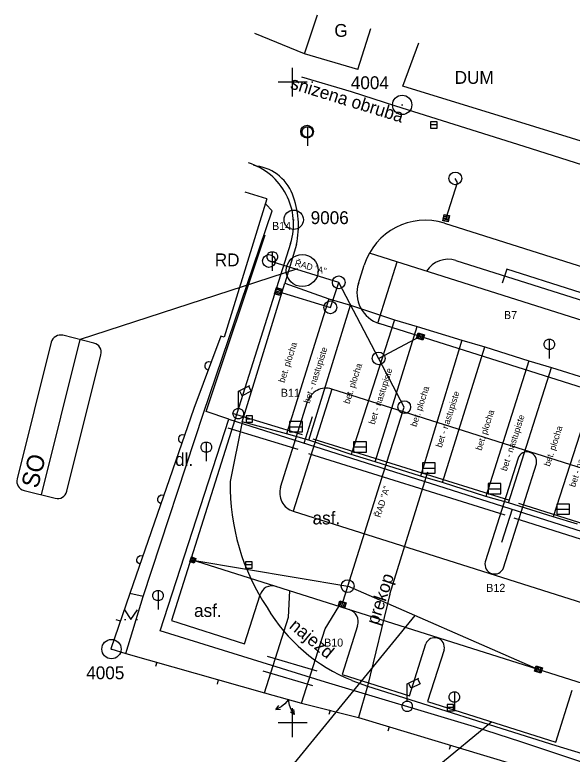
# Model space of a CAD drawing. Extents: x -733601 to -733291, y -1137892 to -1137187.
# Drawn here: x -733521.7 to -733478.2, y -1137552.5 to -1137494.7 of the extents above; entities that cross this region are included whole.
import ezdxf

# ---------------------------------------------------------------- set-up
doc = ezdxf.new("R2010")
doc.units = 0
for name, color, linetype in [('BP_NOVE_NAVRH', 7, 'Continuous'), ('BP_PBPP_pouzito_pro_map_podklady', 7, 'Continuous'), ('Default', 7, 'Continuous'), ('Krizky_Hektom_sit', 7, 'Continuous'), ('SIT_PROJ', 7, 'Continuous'), ('SIT_PUV_BUS', 7, 'Continuous')]:
    doc.layers.add(name, color=color, linetype=linetype)

# ---------------------------------------------------------------- blocks, each defined once
blk = doc.blocks.new('DOPRAVA_4$0$SYMB1230')
at = {"layer": 'Default'}
for p, q in [((-0.1, -0.329897), (-0.1, -0.020619)), ((-0.1, -0.325773), (-0.1, -0.329897)), ((0, -0.020619), (0, -0.329897)), ((0.1, -0.020619), (0.1, -0.329897))]:
    blk.add_line(p, q, dxfattribs=at)
for points in [[(-0.2, 0), (0.2, 0), (0.2, -0.35), (-0.2, -0.35)], [(-0.182831, -0.020619), (0.181696, -0.020619), (0.181696, -0.329897), (-0.182831, -0.329897)]]:
    blk.add_lwpolyline(points, close=True, dxfattribs=at)
blk = doc.blocks.new('T_PS_1_1_4')
at = {"layer": 'Default'}
blk.add_line((-0.01249, 0.00372), (0.01249, 0.00372), dxfattribs=at)
for points in [[(0.01099, 0.008), (-0.01099, 0.008)], [(-0.01249, 0.0065), (-0.01249, 0.0015)], [(0.01249, 0.0015), (0.01249, 0.0065)], [(-0.01099, 0), (0.01099, 0)]]:
    blk.add_lwpolyline(points, dxfattribs=at)
for centre, start, end in [((-0.01099, 0.0065), 90, 180), ((0.01099, 0.0065), 0, 90), ((-0.01099, 0.0015), 180, 270), ((0.01099, 0.0015), 270, 360)]:
    blk.add_arc(centre, 0.0015, start, end, dxfattribs=at)
blk.add_text('SO', height=0.0027, dxfattribs=at).set_placement((-0.01175, 0.00447))

msp = doc.modelspace()

# ---------------------------------------------------------------- linework, layer by layer
at = {"layer": 'BP_NOVE_NAVRH'}
for p, q in [((-733491.493, -1137501.774), (-733491.393, -1137501.774)), ((-733514.2, -1137544.252), (-733514.1, -1137544.252))]:
    msp.add_line(p, q, dxfattribs=at)
for centre in [(-733491.443, -1137501.774), (-733514.15, -1137544.252)]:
    msp.add_circle(centre, 0.756, dxfattribs=at)
at = {"layer": 'BP_PBPP_pouzito_pro_map_podklady'}
msp.add_line((-733499.967, -1137510.74), (-733499.867, -1137510.74), dxfattribs=at)
msp.add_circle((-733499.917, -1137510.74), 0.756, dxfattribs=at)
at = {"layer": 'Krizky_Hektom_sit'}
for p, q in [((-733500, -1137501.131), (-733500, -1137498.869)), ((-733498.869, -1137500), (-733501.131, -1137500)), ((-733500, -1137551.131), (-733500, -1137548.869)), ((-733498.869, -1137550), (-733501.131, -1137550))]:
    msp.add_line(p, q, dxfattribs=at)
at = {"layer": 'SIT_PROJ'}
for p, q in [((-733493.346, -1137518.8), (-733491.839, -1137514.036)), ((-733460.095, -1137529.321), (-733493.227, -1137518.841)), ((-733468.341, -1137533.006), (-733496.944, -1137523.958)), ((-733499.96, -1137533.492), (-733471.356, -1137542.54)), ((-733466.004, -1137550.526), (-733507.966, -1137537.253)), ((-733488.17, -1137544.301), (-733489.452, -1137548.353)), ((-733479.441, -1137551.52), (-733478.159, -1137547.468)), ((-733489.452, -1137548.353), (-733479.441, -1137551.52))]:
    msp.add_line(p, q, dxfattribs=at)
for points in [[(-733488.011, -1137510.618), (-733487.131, -1137507.826), (-733487.294, -1137507.513)], [(-733488.129, -1137511.014), (-733456.405, -1137521.049)], [(-733504.974, -1137526.312), (-733506.751, -1137525.715), (-733502.147, -1137511.903)], [(-733500.165, -1137512.59), (-733509.474, -1137542.02), (-733503.754, -1137543.829), (-733502.547, -1137540.016)], [(-733460.747, -1137528.066), (-733459.541, -1137524.252), (-733494.007, -1137513.35)], [(-733495.699, -1137539.339), (-733491.28, -1137525.366), (-733496.396, -1137515.626), (-733501.847, -1137513.955)], [(-733487.24, -1137513.917), (-733456.681, -1137523.583)], [(-733494.857, -1137515.703), (-733494.405, -1137514.273)], [(-733499.608, -1137514.568), (-733516.593, -1137520.098), (-733516.593, -1137520.098)], [(-733452.807, -1137531.541), (-733451.767, -1137530.574), (-733451.693, -1137528.596), (-733452.588, -1137526.208), (-733454.078, -1137524.418), (-733455.407, -1137523.545), (-733457.093, -1137522.916), (-733483.255, -1137514.587), (-733483.623, -1137515.683)], [(-733501.123, -1137516.343), (-733497.054, -1137517.578), (-733496.396, -1137515.626)], [(-733490.03, -1137519.859), (-733493.277, -1137521.563)], [(-733496.944, -1137523.958), (-733499.96, -1137533.492)], [(-733500.937, -1137531.61), (-733498.826, -1137524.936)], [(-733504.713, -1137525.84), (-733499.246, -1137527.493)], [(-733452.807, -1137531.541), (-733452.473, -1137533.224), (-733457.478, -1137552.932), (-733458.231, -1137552.948), (-733457.677, -1137553.487), (-733458.16, -1137554.567), (-733458.792, -1137555.404), (-733459.851, -1137556.172), (-733461, -1137556.688), (-733462.364, -1137556.956), (-733463.762, -1137556.963), (-733467.652, -1137556.198), (-733471.45, -1137555.042), (-733482.168, -1137551.478), (-733485.798, -1137550.329), (-733497.445, -1137546.837), (-733510.353, -1137542.814), (-733504.974, -1137526.312), (-733469.528, -1137537.558), (-733468.34, -1137535.665)], [(-733499.11, -1137528.173), (-733498.437, -1137526.097)], [(-733505.06, -1137526.988), (-733499.593, -1137528.642)], [(-733498.412, -1137527.836), (-733483.061, -1137532.622)], [(-733498.769, -1137528.982), (-733483.418, -1137533.768)], [(-733482.392, -1137529.348), (-733484.955, -1137537.452)], [(-733483.525, -1137537.904), (-733480.961, -1137529.8)], [(-733482.363, -1137532.866), (-733469.375, -1137536.976)], [(-733482.84, -1137533.332), (-733483.673, -1137535.931)], [(-733482.725, -1137534.01), (-733469.737, -1137538.12)], [(-733507.799, -1137537.306), (-733495.699, -1137539.339)], [(-733496.132, -1137540.766), (-733495.699, -1137539.339)], [(-733480.816, -1137545.848), (-733495.699, -1137539.339)], [(-733502.2, -1137547.67), (-733500.332, -1137541.765), (-733500.206, -1137539.708)], [(-733499.3, -1137548.47), (-733497.466, -1137542.672), (-733496.386, -1137540.916)], [(-733490.453, -1137541.633), (-733507.315, -1137562.262), (-733507.315, -1137562.262)], [(-733494.92, -1137542.428), (-733496.126, -1137546.242), (-733490.882, -1137547.901), (-733489.601, -1137543.849)], [(-733501.976, -1137544.806), (-733498.103, -1137545.946)], [(-733502.315, -1137545.957), (-733498.442, -1137547.097)], [(-733484.447, -1137549.937), (-733501.629, -1137564.088), (-733501.629, -1137564.088)]]:
    msp.add_lwpolyline(points, dxfattribs=at)
for centre, radius in [((-733498.87, -1137503.86), 0.5), ((-733487.294, -1137507.513), 0.5), ((-733501.847, -1137513.955), 0.5), ((-733499.246, -1137514.708), 1.25), ((-733496.396, -1137515.626), 0.5), ((-733497.054, -1137517.578), 0.5), ((-733493.277, -1137521.563), 0.5), ((-733491.28, -1137525.366), 0.5), ((-733495.699, -1137539.339), 0.5)]:
    msp.add_circle(centre, radius, dxfattribs=at)
for centre, radius, start, end in [((-733504.933, -1137511.082), 5, 342.44706, 72.81961), ((-733489.637, -1137515.781), 5, 72.44709, 162.44705), ((-733487.843, -1137515.824), 2, 72.44714, 147.96949), ((-733492.473, -1137516.457), 2.5, 162.44706, 252.44712), ((-733497.396, -1137525.388), 1.5, 72.44702, 162.44712), ((-733481.688, -1137529.611), 0.751, 345.40417, 159.48997), ((-733499.507, -1137532.062), 1.5, 162.44702, 252.44712), ((-733484.228, -1137537.641), 0.751, 165.40421, 339.48993), ((-733501.594, -1137540.317), 1, 72.44718, 162.44698), ((-733495.873, -1137542.127), 1, 342.44712, 72.44699), ((-733488.897, -1137544.112), 0.751, 345.40416, 159.48998)]:
    msp.add_arc(centre, radius, start, end, dxfattribs=at)
at = {"layer": 'SIT_PUV_BUS'}
for p, q in [((-733499.06, -1137497.79), (-733498.07, -1137494.74)), ((-733494.9, -1137499), (-733493.89, -1137495.81)), ((-733499.06, -1137497.79), (-733502.94, -1137496.21)), ((-733491.4, -1137500.31), (-733490.15, -1137496.94)), ((-733494.9, -1137499), (-733499.06, -1137497.79)), ((-733499.31, -1137499.59), (-733495.44, -1137500.73)), ((-733482.5, -1137503.04), (-733491.4, -1137500.31)), ((-733495.44, -1137500.73), (-733491.97, -1137501.84)), ((-733491.97, -1137501.84), (-733481.95, -1137504.99)), ((-733499.25, -1137503.78), (-733499.15, -1137503.58)), ((-733499.15, -1137503.58), (-733498.95, -1137503.48)), ((-733498.95, -1137503.48), (-733498.75, -1137503.48)), ((-733498.85, -1137503.48), (-733498.85, -1137504.98)), ((-733498.75, -1137503.48), (-733498.55, -1137503.58)), ((-733498.55, -1137503.58), (-733498.45, -1137503.78)), ((-733488.72, -1137503.09), (-733489.22, -1137503.09)), ((-733489.22, -1137503.09), (-733489.22, -1137503.59)), ((-733488.72, -1137503.34), (-733489.22, -1137503.34)), ((-733488.72, -1137503.59), (-733488.72, -1137503.09)), ((-733463.96, -1137508.84), (-733482.5, -1137503.04)), ((-733499.25, -1137503.98), (-733499.25, -1137503.78)), ((-733499.15, -1137504.18), (-733499.25, -1137503.98)), ((-733498.45, -1137503.98), (-733498.55, -1137504.18)), ((-733498.45, -1137503.78), (-733498.45, -1137503.98)), ((-733489.22, -1137503.59), (-733488.72, -1137503.59)), ((-733498.95, -1137504.28), (-733499.15, -1137504.18)), ((-733498.75, -1137504.28), (-733498.95, -1137504.28)), ((-733498.55, -1137504.18), (-733498.75, -1137504.28)), ((-733481.95, -1137504.99), (-733464.81, -1137510.43)), ((-733502.01, -1137509.1), (-733503.7, -1137508.59)), ((-733502.01, -1137509.1), (-733505.35, -1137519.91)), ((-733501.6, -1137510.04), (-733502.1, -1137509.52)), ((-733506.97, -1137525.84), (-733501.6, -1137510.04)), ((-733499.71, -1137512.68), (-733500.61, -1137515.7)), ((-733501.99, -1137513.53), (-733501.89, -1137513.33)), ((-733501.89, -1137513.33), (-733501.69, -1137513.23)), ((-733501.69, -1137513.23), (-733501.49, -1137513.23)), ((-733501.59, -1137513.23), (-733501.59, -1137514.73)), ((-733501.49, -1137513.23), (-733501.29, -1137513.33)), ((-733501.29, -1137513.33), (-733501.19, -1137513.53)), ((-733501.99, -1137513.73), (-733501.99, -1137513.53)), ((-733501.89, -1137513.93), (-733501.99, -1137513.73)), ((-733501.69, -1137514.03), (-733501.89, -1137513.93)), ((-733501.29, -1137513.93), (-733501.49, -1137514.03)), ((-733501.19, -1137513.73), (-733501.29, -1137513.93)), ((-733501.19, -1137513.53), (-733501.19, -1137513.73)), ((-733501.49, -1137514.03), (-733501.69, -1137514.03)), ((-733503.93, -1137526.52), (-733500.61, -1137515.7)), ((-733500.61, -1137515.7), (-733497.17, -1137516.92)), ((-733497.17, -1137516.92), (-733500.49, -1137527.44)), ((-733498.73, -1137527.95), (-733495.49, -1137517.4)), ((-733497.17, -1137516.92), (-733495.49, -1137517.4)), ((-733495.49, -1137517.4), (-733492.03, -1137518.54)), ((-733492.03, -1137518.54), (-733495.44, -1137529.07)), ((-733492.03, -1137518.54), (-733490.26, -1137519.06)), ((-733493.55, -1137529.63), (-733490.26, -1137519.06)), ((-733490.26, -1137519.06), (-733486.79, -1137520.15)), ((-733505.61, -1137519.82), (-733507.73, -1137525.48)), ((-733505.35, -1137519.91), (-733505.61, -1137519.82)), ((-733486.79, -1137520.15), (-733490.02, -1137530.76)), ((-733486.79, -1137520.15), (-733484.99, -1137520.66)), ((-733480.35, -1137520.36), (-733480.25, -1137520.16)), ((-733480.25, -1137520.16), (-733480.05, -1137520.06)), ((-733480.05, -1137520.06), (-733479.85, -1137520.06)), ((-733479.95, -1137520.06), (-733479.95, -1137521.56)), ((-733479.85, -1137520.06), (-733479.65, -1137520.16)), ((-733479.65, -1137520.16), (-733479.55, -1137520.36)), ((-733488.3, -1137531.25), (-733484.99, -1137520.66)), ((-733484.99, -1137520.66), (-733481.54, -1137521.76)), ((-733480.35, -1137520.56), (-733480.35, -1137520.36)), ((-733480.25, -1137520.76), (-733480.35, -1137520.56)), ((-733480.05, -1137520.86), (-733480.25, -1137520.76)), ((-733479.85, -1137520.86), (-733480.05, -1137520.86)), ((-733479.65, -1137520.76), (-733479.85, -1137520.86)), ((-733479.55, -1137520.56), (-733479.65, -1137520.76)), ((-733479.55, -1137520.36), (-733479.55, -1137520.56)), ((-733506.835, -1137522.084), (-733506.8, -1137521.991)), ((-733506.8, -1137521.991), (-733506.701, -1137521.868)), ((-733506.701, -1137521.868), (-733506.572, -1137521.809)), ((-733506.572, -1137521.809), (-733506.367, -1137521.832)), ((-733481.54, -1137521.76), (-733484.92, -1137532.35)), ((-733481.54, -1137521.76), (-733479.77, -1137522.27)), ((-733506.841, -1137522.242), (-733506.835, -1137522.084)), ((-733506.782, -1137522.371), (-733506.841, -1137522.242)), ((-733506.613, -1137522.488), (-733506.782, -1137522.371)), ((-733483.15, -1137532.83), (-733479.77, -1137522.27)), ((-733479.77, -1137522.27), (-733476.26, -1137523.39)), ((-733504.24, -1137524.12), (-733503.34, -1137523.67)), ((-733503.44, -1137523.72), (-733503.24, -1137524.12)), ((-733476.26, -1137523.39), (-733479.65, -1137533.93)), ((-733504.24, -1137525.47), (-733504.24, -1137524.12)), ((-733503.94, -1137524.47), (-733504.14, -1137524.07)), ((-733503.24, -1137524.12), (-733503.94, -1137524.47)), ((-733507.73, -1137525.48), (-733512.71, -1137539.92)), ((-733504.54, -1137525.57), (-733504.34, -1137525.47)), ((-733504.34, -1137525.47), (-733504.14, -1137525.47)), ((-733504.14, -1137525.47), (-733503.94, -1137525.57)), ((-733511.67, -1137540.14), (-733506.97, -1137525.84)), ((-733504.64, -1137525.77), (-733504.54, -1137525.57)), ((-733504.64, -1137525.97), (-733504.64, -1137525.77)), ((-733504.54, -1137526.17), (-733504.64, -1137525.97)), ((-733503.94, -1137525.57), (-733503.84, -1137525.77)), ((-733503.84, -1137525.97), (-733503.94, -1137526.17)), ((-733503.84, -1137525.77), (-733503.84, -1137525.97)), ((-733503.13, -1137526.05), (-733503.63, -1137526.05)), ((-733503.63, -1137526.05), (-733503.63, -1137526.55)), ((-733503.13, -1137526.55), (-733503.13, -1137526.05)), ((-733503.93, -1137526.52), (-733504.87, -1137531.18)), ((-733504.34, -1137526.27), (-733504.54, -1137526.17)), ((-733504.14, -1137526.27), (-733504.34, -1137526.27)), ((-733503.94, -1137526.17), (-733504.14, -1137526.27)), ((-733500.49, -1137527.44), (-733503.93, -1137526.52)), ((-733503.13, -1137526.3), (-733503.63, -1137526.3)), ((-733503.63, -1137526.55), (-733503.13, -1137526.55)), ((-733499.24, -1137526.49), (-733500.24, -1137526.49)), ((-733500.24, -1137526.49), (-733500.24, -1137527.29)), ((-733499.24, -1137527.29), (-733499.24, -1137526.49)), ((-733500.24, -1137526.89), (-733499.24, -1137526.89)), ((-733508.899, -1137527.941), (-733508.897, -1137527.783)), ((-733508.897, -1137527.783), (-733508.864, -1137527.688)), ((-733508.864, -1137527.688), (-733508.768, -1137527.563)), ((-733508.768, -1137527.563), (-733508.641, -1137527.501)), ((-733508.641, -1137527.501), (-733508.435, -1137527.519)), ((-733498.73, -1137527.95), (-733500.49, -1137527.44)), ((-733500.24, -1137527.29), (-733499.24, -1137527.29)), ((-733508.837, -1137528.068), (-733508.899, -1137527.941)), ((-733508.665, -1137528.181), (-733508.837, -1137528.068)), ((-733507.15, -1137528.39), (-733507.05, -1137528.19)), ((-733507.15, -1137528.59), (-733507.15, -1137528.39)), ((-733507.05, -1137528.19), (-733506.85, -1137528.09)), ((-733506.85, -1137528.09), (-733506.65, -1137528.09)), ((-733506.75, -1137528.09), (-733506.75, -1137529.59)), ((-733506.65, -1137528.09), (-733506.45, -1137528.19)), ((-733506.45, -1137528.19), (-733506.35, -1137528.39)), ((-733506.35, -1137528.39), (-733506.35, -1137528.59)), ((-733495.44, -1137529.07), (-733498.73, -1137527.95)), ((-733494.24, -1137528.07), (-733495.24, -1137528.07)), ((-733495.24, -1137528.07), (-733495.24, -1137528.87)), ((-733494.24, -1137528.87), (-733494.24, -1137528.07)), ((-733507.05, -1137528.79), (-733507.15, -1137528.59)), ((-733506.85, -1137528.89), (-733507.05, -1137528.79)), ((-733506.65, -1137528.89), (-733506.85, -1137528.89)), ((-733506.45, -1137528.79), (-733506.65, -1137528.89)), ((-733506.35, -1137528.59), (-733506.45, -1137528.79)), ((-733495.24, -1137528.47), (-733494.24, -1137528.47)), ((-733495.24, -1137528.87), (-733494.24, -1137528.87)), ((-733493.55, -1137529.63), (-733495.44, -1137529.07)), ((-733490.02, -1137530.76), (-733493.55, -1137529.63)), ((-733488.86, -1137529.72), (-733489.86, -1137529.72)), ((-733489.86, -1137529.72), (-733489.86, -1137530.52)), ((-733489.86, -1137530.12), (-733488.86, -1137530.12)), ((-733488.86, -1137530.52), (-733488.86, -1137529.72)), ((-733492.41, -1137539.97), (-733489.45, -1137530.42)), ((-733489.86, -1137530.52), (-733488.86, -1137530.52)), ((-733488.3, -1137531.25), (-733490.02, -1137530.76)), ((-733484.92, -1137532.35), (-733488.3, -1137531.25)), ((-733483.73, -1137531.33), (-733484.73, -1137531.33)), ((-733484.73, -1137531.33), (-733484.73, -1137532.13)), ((-733484.73, -1137531.73), (-733483.73, -1137531.73)), ((-733483.73, -1137532.13), (-733483.73, -1137531.33)), ((-733510.527, -1137532.503), (-733510.494, -1137532.408)), ((-733510.494, -1137532.408), (-733510.398, -1137532.283)), ((-733510.398, -1137532.283), (-733510.271, -1137532.221)), ((-733510.271, -1137532.221), (-733510.065, -1137532.239)), ((-733483.15, -1137532.83), (-733484.92, -1137532.35)), ((-733484.73, -1137532.13), (-733483.73, -1137532.13)), ((-733510.529, -1137532.661), (-733510.527, -1137532.503)), ((-733510.467, -1137532.788), (-733510.529, -1137532.661)), ((-733510.295, -1137532.901), (-733510.467, -1137532.788)), ((-733479.65, -1137533.93), (-733483.15, -1137532.83)), ((-733478.37, -1137532.93), (-733479.37, -1137532.93)), ((-733479.37, -1137532.93), (-733479.37, -1137533.73)), ((-733478.37, -1137533.73), (-733478.37, -1137532.93)), ((-733479.37, -1137533.33), (-733478.37, -1137533.33)), ((-733477.76, -1137534.51), (-733479.65, -1137533.93)), ((-733479.37, -1137533.73), (-733478.37, -1137533.73)), ((-733512.124, -1137537.138), (-733512.028, -1137537.013)), ((-733512.028, -1137537.013), (-733511.901, -1137536.951)), ((-733511.901, -1137536.951), (-733511.695, -1137536.969)), ((-733512.159, -1137537.391), (-733512.157, -1137537.233)), ((-733512.097, -1137537.518), (-733512.159, -1137537.391)), ((-733512.157, -1137537.233), (-733512.124, -1137537.138)), ((-733511.925, -1137537.631), (-733512.097, -1137537.518)), ((-733503.17, -1137537.43), (-733503.67, -1137537.43)), ((-733503.67, -1137537.43), (-733503.67, -1137537.93)), ((-733503.17, -1137537.93), (-733503.17, -1137537.43)), ((-733503.17, -1137537.68), (-733503.67, -1137537.68)), ((-733503.67, -1137537.93), (-733503.17, -1137537.93)), ((-733512.71, -1137539.92), (-733514.19, -1137544.24)), ((-733511.67, -1137540.14), (-733512.71, -1137539.92)), ((-733510.91, -1137539.97), (-733510.81, -1137539.77)), ((-733510.81, -1137539.77), (-733510.61, -1137539.67)), ((-733510.61, -1137539.67), (-733510.41, -1137539.67)), ((-733510.51, -1137539.67), (-733510.51, -1137541.17)), ((-733510.41, -1137539.67), (-733510.21, -1137539.77)), ((-733510.21, -1137539.77), (-733510.11, -1137539.97)), ((-733513.02, -1137544.59), (-733511.67, -1137540.14)), ((-733510.91, -1137540.17), (-733510.91, -1137539.97)), ((-733510.81, -1137540.37), (-733510.91, -1137540.17)), ((-733510.61, -1137540.47), (-733510.81, -1137540.37)), ((-733510.41, -1137540.47), (-733510.61, -1137540.47)), ((-733510.21, -1137540.37), (-733510.41, -1137540.47)), ((-733510.11, -1137540.17), (-733510.21, -1137540.37)), ((-733510.11, -1137539.97), (-733510.11, -1137540.17)), ((-733492.41, -1137539.97), (-733494.16, -1137547.14)), ((-733513.13, -1137541.18), (-733512.63, -1137541.93)), ((-733512.63, -1137541.93), (-733512.13, -1137541.18)), ((-733513.45, -1137542.08), (-733513.781, -1137541.967)), ((-733513.13, -1137541.93), (-733513.03, -1137541.93)), ((-733512.23, -1137541.93), (-733512.13, -1137541.93)), ((-733514.19, -1137544.24), (-733513.02, -1137544.59)), ((-733513.02, -1137544.59), (-733502.2, -1137547.67)), ((-733510.62, -1137545.28), (-733510.715, -1137545.617)), ((-733505.81, -1137546.64), (-733505.905, -1137546.977)), ((-733495.38, -1137546.69), (-733494.16, -1137547.14)), ((-733491.05, -1137546.96), (-733490.15, -1137546.51)), ((-733490.25, -1137546.56), (-733490.05, -1137546.96)), ((-733494.16, -1137547.14), (-733494.85, -1137549.6)), ((-733494.16, -1137547.14), (-733479.43, -1137551.77)), ((-733491.05, -1137548.31), (-733491.05, -1137546.96)), ((-733490.75, -1137547.31), (-733490.95, -1137546.91)), ((-733490.05, -1137546.96), (-733490.75, -1137547.31)), ((-733502.2, -1137547.67), (-733499.3, -1137548.47)), ((-733487.76, -1137547.9), (-733487.66, -1137547.7)), ((-733487.76, -1137548.1), (-733487.76, -1137547.9)), ((-733487.66, -1137547.7), (-733487.46, -1137547.6)), ((-733487.46, -1137547.6), (-733487.26, -1137547.6)), ((-733487.36, -1137547.6), (-733487.36, -1137549.1)), ((-733487.26, -1137547.6), (-733487.06, -1137547.7)), ((-733487.06, -1137547.7), (-733486.96, -1137547.9)), ((-733486.96, -1137547.9), (-733486.96, -1137548.1)), ((-733500.619, -1137548.522), (-733500.892, -1137548.758)), ((-733500.32, -1137548.19), (-733500.619, -1137548.522)), ((-733500.234, -1137548.629), (-733500.32, -1137548.19)), ((-733499.3, -1137548.47), (-733494.85, -1137549.6)), ((-733491.45, -1137548.61), (-733491.35, -1137548.41)), ((-733491.35, -1137548.41), (-733491.15, -1137548.31)), ((-733491.15, -1137548.31), (-733490.95, -1137548.31)), ((-733490.95, -1137548.31), (-733490.75, -1137548.41)), ((-733490.75, -1137548.41), (-733490.65, -1137548.61)), ((-733487.44, -1137548.57), (-733487.94, -1137548.57)), ((-733487.94, -1137548.57), (-733487.94, -1137549.07)), ((-733487.66, -1137548.3), (-733487.76, -1137548.1)), ((-733487.46, -1137548.4), (-733487.66, -1137548.3)), ((-733487.26, -1137548.4), (-733487.46, -1137548.4)), ((-733487.44, -1137549.07), (-733487.44, -1137548.57)), ((-733487.06, -1137548.3), (-733487.26, -1137548.4)), ((-733486.96, -1137548.1), (-733487.06, -1137548.3)), ((-733501.309, -1137548.954), (-733501.071, -1137548.657)), ((-733500.892, -1137548.758), (-733501.309, -1137548.954)), ((-733501.309, -1137548.954), (-733500.945, -1137548.951)), ((-733500.121, -1137548.971), (-733500.234, -1137548.629)), ((-733499.863, -1137549.354), (-733500.174, -1137549.164)), ((-733499.863, -1137549.354), (-733500.121, -1137548.971)), ((-733499.863, -1137549.354), (-733499.915, -1137548.976)), ((-733497.08, -1137549.03), (-733497.166, -1137549.369)), ((-733491.45, -1137548.81), (-733491.45, -1137548.61)), ((-733491.35, -1137549.01), (-733491.45, -1137548.81)), ((-733491.15, -1137549.11), (-733491.35, -1137549.01)), ((-733490.95, -1137549.11), (-733491.15, -1137549.11)), ((-733490.75, -1137549.01), (-733490.95, -1137549.11)), ((-733490.65, -1137548.81), (-733490.75, -1137549.01)), ((-733490.65, -1137548.61), (-733490.65, -1137548.81)), ((-733487.44, -1137548.82), (-733487.94, -1137548.82)), ((-733487.94, -1137549.07), (-733487.44, -1137549.07)), ((-733494.85, -1137549.6), (-733480.06, -1137554.03)), ((-733492.46, -1137550.32), (-733492.561, -1137550.655)), ((-733487.67, -1137551.75), (-733487.771, -1137552.085)), ((-733479.43, -1137551.77), (-733466.01, -1137555.88))]:
    msp.add_line(p, q, dxfattribs=at)
for centre, radius, start, end in [((-733503.29, -1137510.03), 3.521, 21.3361, 86.1448), ((-733506.18, -1137511.2), 6.64, 347.09298, 21.70443), ((-733487.65, -1137531.48), 17.227, 179.00184, 213.61382), ((-733490.32, -1137534.09), 13.576, 210.67944, 248.10941)]:
    msp.add_arc(centre, radius, start, end, dxfattribs=at)

# ---------------------------------------------------------------- block references
at = {"layer": 'SIT_PROJ'}
for name, p, xscale, yscale, rotation in [('DOPRAVA_4$0$SYMB1230', (-733488.226, -1137510.574), 1.25, 1.2500000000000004, 78.19096299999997), ('DOPRAVA_4$0$SYMB1230', (-733501.332, -1137516.277), 1.25, 1.2499999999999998, 72.618872), ('T_PS_1_1_4', (-733516.307, -1137526.606), 499.9999999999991, 499.99999999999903, 75.93557209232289), ('DOPRAVA_4$0$SYMB1230', (-733489.943, -1137519.65), 1.25, 1.2500000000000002, -17.55281900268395), ('DOPRAVA_4$0$SYMB1230', (-733496.198, -1137540.975), 1.25, 1.25, 162.44707136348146), ('DOPRAVA_4$0$SYMB1230', (-733480.858, -1137546.057), 1.25, 1.25, 162.850086)]:
    msp.add_blockref(name, p, dxfattribs=dict(at, xscale=xscale, yscale=yscale, rotation=rotation))
at = {"layer": 'SIT_PROJ', "rotation": 72.4470728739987}
msp.add_blockref('DOPRAVA_4$0$SYMB1230', (-733507.966, -1137537.253), dxfattribs=at)

# ---------------------------------------------------------------- texts
at = {"layer": 'BP_NOVE_NAVRH'}
for s, p in [('4004', (-733495.454, -1137500.541)), ('4005', (-733516.122, -1137546.604))]:
    msp.add_text(s, height=1, dxfattribs=at).set_placement(p)
at = {"layer": 'BP_PBPP_pouzito_pro_map_podklady'}
msp.add_text('9006', height=1, dxfattribs=at).set_placement((-733498.591, -1137511.076))
at = {"layer": 'SIT_PROJ'}
for s, height, rotation, p in [('B14', 0.625, 360, (-733501.608, -1137511.536)), ('ŘAD "A"', 0.5, 344.14619, (-733499.868, -1137514.325)), ('B7', 0.625, 360, (-733483.49, -1137518.491)), ('B11', 0.625, 360, (-733500.918, -1137524.558)), ('ŘAD "A"', 0.5, 72.75725, (-733493.141, -1137534.023)), ('B12', 0.625, 360, (-733484.873, -1137539.785)), ('B10', 0.625, 360, (-733497.54, -1137544.057))]:
    msp.add_text(s, height=height, rotation=rotation, dxfattribs=at).set_placement(p)
at = {"layer": 'SIT_PUV_BUS'}
for s, p in [('G', (-733496.74, -1137496.46)), ('DUM', (-733487.34, -1137500.13)), ('RD', (-733506.08, -1137514.37)), ('dl.', (-733509.18, -1137529.95)), ('asf.', (-733498.44, -1137534.52)), ('asf.', (-733507.7, -1137541.74))]:
    msp.add_text(s, height=1, dxfattribs=at).set_placement(p)
for s, height, rotation, p in [('snizena obruba', 1, 342.9, (-733500.25, -1137500.48)), ('bet. plocha', 0.5, 72, (-733500.65, -1137523.5)), ('bet - nastupiste', 0.5, 72, (-733498.68, -1137525.12)), ('bet. plocha', 0.5, 72, (-733495.57, -1137525.15)), ('bet - nastupiste', 0.5, 72, (-733493.6, -1137526.76)), ('bet. plocha', 0.5, 72, (-733490.33, -1137526.94)), ('bet - nastupiste', 0.5, 72, (-733488.36, -1137528.56)), ('bet. plocha', 0.5, 72, (-733485.25, -1137528.79)), ('bet - nastupiste', 0.5, 72, (-733483.28, -1137530.4)), ('bet. plocha', 0.5, 72, (-733479.91, -1137530.03)), ('bet - nastupiste', 0.5, 72, (-733477.93, -1137531.65)), ('prekop', 1, 72, (-733493.33, -1137542.43)), ('najezd', 1, 320.4, (-733500.33, -1137542.56))]:
    msp.add_text(s, height=height, rotation=rotation, dxfattribs=at).set_placement(p)

doc.saveas('drawing.dxf')
